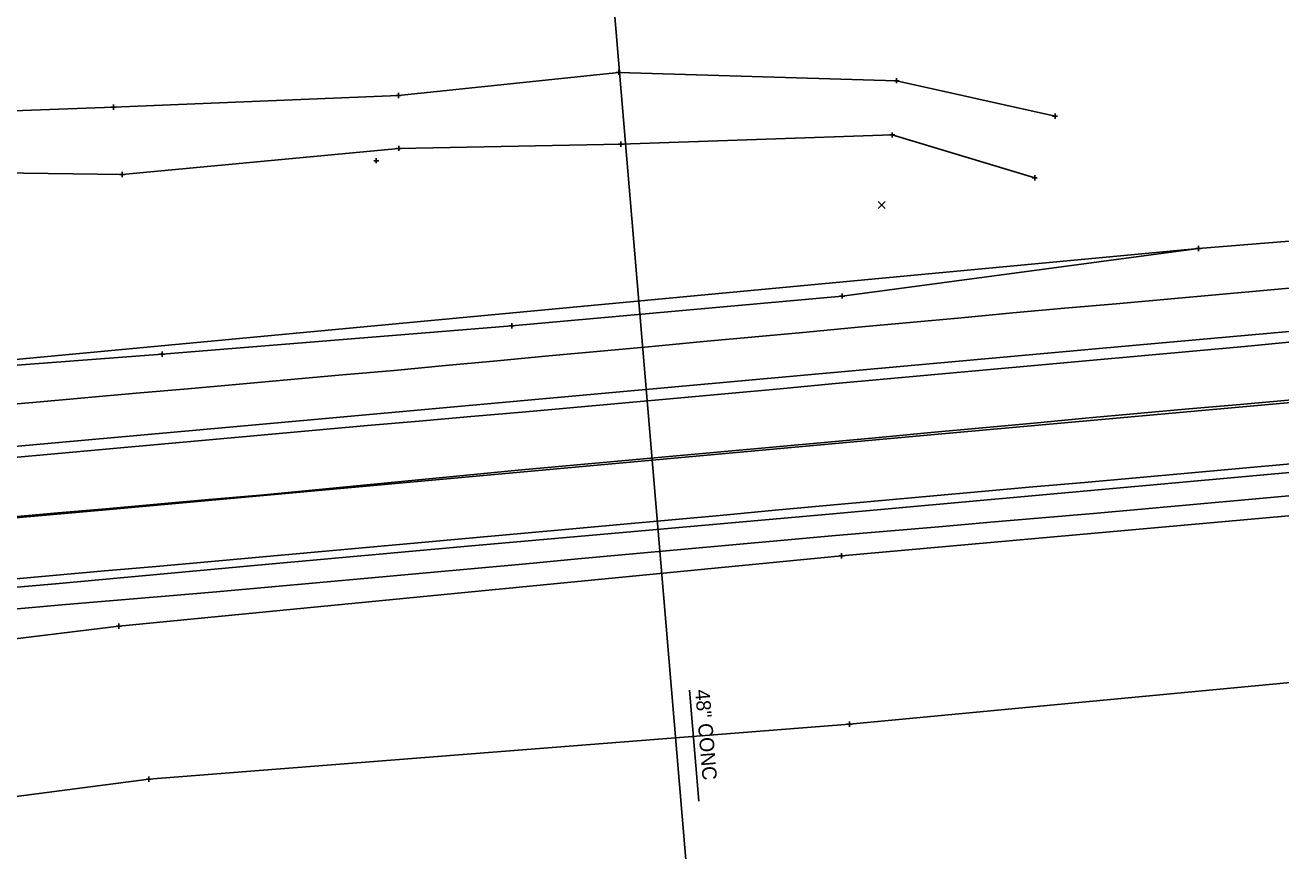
# Model space of a CAD drawing. Extents: x 207090 to 277928, y 600777 to 621109.
# Drawn here: x 261434.3 to 261676.8, y 612208.4 to 612367.8 of the extents above; entities that cross this region are included whole.
import ezdxf

# ---------------------------------------------------------------- set-up
doc = ezdxf.new("R2010")
doc.units = 0
for name, color, linetype in [('DR_X_Ditch', 7, 'Continuous'), ('DR_X_Storm_Sewer', 7, 'Continuous'), ('DR_X_Text', 7, 'Continuous'), ('PM_P_Edge_Line', 7, 'Continuous'), ('PM_P_Stop_Line', 7, 'Continuous'), ('PM_X_Edge_Line', 7, 'Continuous'), ('PM_X_Lane_Line', 7, 'Continuous'), ('PV_X_COP', 7, 'Continuous'), ('PV_X_EOP', 7, 'Continuous'), ('PV_X_Shoulder_Rumble_Strip', 7, 'Continuous'), ('SC_ProfileRun2', 7, 'Continuous'), ('SV_X_Toe_of_Slope', 7, 'Continuous')]:
    doc.layers.add(name, color=color, linetype=linetype)

msp = doc.modelspace()

# ---------------------------------------------------------------- linework, layer by layer
at = {"layer": 'DR_X_Ditch'}
msp.add_lwpolyline([(261203.79, 612197.21), (261326.07, 612205.04), (261458.14, 612222.26), (261593.47, 612232.9), (261720.84, 612244.93), (261848.4, 612257.12), (261858.55, 612256.91)], dxfattribs=at)
at = {"layer": 'DR_X_Storm_Sewer'}
msp.add_line((261547.33, 612379.42), (261572.44, 612081.43), dxfattribs=at)
at = {"layer": 'DR_X_Text'}
msp.add_line((261564.35, 612218), (261562.54, 612239.45), dxfattribs=at)
at = {"layer": 'PM_P_Edge_Line'}
for points in [[(261194.23, 612211.46), (261326.93, 612217.65), (261370.14, 612241.77), (261452.37, 612251.81), (261591.95, 612265.36), (261714.92, 612276.39), (261857.94, 612285.81), (262004.26, 612302.21), (262139.05, 612311.28), (262277.89, 612327.47), (262423.18, 612340.98), (262554.31, 612350.26), (262686.32, 612362.25)], [(261633.15, 612350.23), (261602.56, 612357.06), (261548.9, 612358.68), (261506.35, 612354.2), (261451.33, 612351.96), (261395.04, 612349.88), (261337.88, 612345.88), (261278.55, 612340.15), (261221.93, 612336.04)], [(262058.53, 612356.83), (261940.84, 612349.68), (261860.82, 612342.07), (261794.21, 612335.5), (261726.89, 612330.02), (261660.87, 612324.68), (261592.06, 612315.51), (261528.23, 612309.75), (261460.75, 612304.3), (261395.26, 612299.36), (261330.21, 612293.39), (261264.57, 612287.95), (261201.55, 612284), (261173.78, 612279.04)], [(261660.87, 612324.68), (261173.78, 612279.04)]]:
    msp.add_lwpolyline(points, dxfattribs=at)
at = {"layer": 'PM_P_Stop_Line'}
for p, q in [((261548.4, 612358.68), (261549.4, 612358.68)), ((261548.9, 612359.18), (261548.9, 612358.18)), ((261548.9, 612358.68), (261548.9, 612358.68)), ((261602.06, 612357.06), (261603.06, 612357.06)), ((261602.56, 612357.56), (261602.56, 612356.56)), ((261602.56, 612357.06), (261602.56, 612357.06)), ((261505.85, 612354.2), (261506.85, 612354.2)), ((261506.35, 612354.7), (261506.35, 612353.7)), ((261506.35, 612354.2), (261506.35, 612354.2)), ((261450.83, 612351.96), (261451.83, 612351.96)), ((261451.33, 612352.46), (261451.33, 612351.46)), ((261451.33, 612351.96), (261451.33, 612351.96)), ((261632.65, 612350.23), (261633.65, 612350.23)), ((261633.15, 612350.73), (261633.15, 612349.73)), ((261633.15, 612350.23), (261633.15, 612350.23)), ((261601.21, 612346.6), (261602.21, 612346.6)), ((261601.71, 612347.1), (261601.71, 612346.1)), ((261601.71, 612346.6), (261601.71, 612346.6)), ((261505.91, 612344.01), (261506.91, 612344.01)), ((261506.41, 612344.51), (261506.41, 612343.51)), ((261506.41, 612344.01), (261506.41, 612344.01)), ((261548.82, 612344.81), (261549.82, 612344.81)), ((261549.32, 612345.31), (261549.32, 612344.31)), ((261549.32, 612344.81), (261549.32, 612344.81)), ((261452.52, 612338.97), (261453.52, 612338.97)), ((261453.02, 612339.47), (261453.02, 612338.47)), ((261453.02, 612338.97), (261453.02, 612338.97)), ((261629.22, 612338.81), (261629.22, 612337.81)), ((261628.72, 612338.31), (261629.72, 612338.31)), ((261629.22, 612338.31), (261629.22, 612338.31)), ((261660.37, 612324.68), (261661.37, 612324.68)), ((261660.87, 612325.18), (261660.87, 612324.18)), ((261660.87, 612324.68), (261660.87, 612324.68)), ((261591.56, 612315.51), (261592.56, 612315.51)), ((261592.06, 612316.01), (261592.06, 612315.01)), ((261592.06, 612315.51), (261592.06, 612315.51)), ((261527.73, 612309.75), (261528.73, 612309.75)), ((261528.23, 612310.25), (261528.23, 612309.25)), ((261528.23, 612309.75), (261528.23, 612309.75)), ((261460.25, 612304.3), (261461.25, 612304.3)), ((261460.75, 612304.8), (261460.75, 612303.8)), ((261460.75, 612304.3), (261460.75, 612304.3)), ((261591.45, 612265.36), (261592.45, 612265.36)), ((261591.95, 612265.86), (261591.95, 612264.86)), ((261591.95, 612265.36), (261591.95, 612265.36)), ((261451.87, 612251.81), (261452.87, 612251.81)), ((261452.37, 612252.31), (261452.37, 612251.31)), ((261452.37, 612251.81), (261452.37, 612251.81)), ((261592.97, 612232.9), (261593.97, 612232.9)), ((261593.47, 612233.4), (261593.47, 612232.4)), ((261593.47, 612232.9), (261593.47, 612232.9)), ((261458.14, 612222.76), (261458.14, 612221.76)), ((261457.64, 612222.26), (261458.64, 612222.26)), ((261458.14, 612222.26), (261458.14, 612222.26))]:
    msp.add_line(p, q, dxfattribs=at)
at = {"layer": 'PM_X_Edge_Line'}
for p, q in [((261599.02, 612332.41), (261600.35, 612333.75)), ((261599.02, 612333.75), (261600.35, 612332.41))]:
    msp.add_line(p, q, dxfattribs=at)
for points in [[(261430.67, 612284.21), (261440.63, 612285.12), (261450.59, 612286.03), (261460.55, 612286.94), (261470.51, 612287.84), (261480.47, 612288.74), (261490.43, 612289.64), (261500.39, 612290.53), (261510.35, 612291.38), (261520.32, 612292.23), (261530.28, 612293.08), (261540.24, 612293.97), (261550.2, 612294.89), (261560.16, 612295.8), (261570.12, 612296.72), (261580.08, 612297.63), (261590.04, 612298.54), (261600, 612299.44), (261609.95, 612300.35), (261619.91, 612301.26), (261629.87, 612302.16), (261639.83, 612303.06), (261649.79, 612303.97), (261659.75, 612304.88), (261669.71, 612305.8), (261679.67, 612306.73)], [(261429.69, 612260.67), (261439.65, 612261.56), (261449.61, 612262.45), (261459.57, 612263.33), (261469.54, 612264.22), (261479.5, 612265.11), (261489.46, 612266.01), (261499.42, 612266.92), (261509.38, 612267.82), (261519.34, 612268.72), (261529.29, 612269.62), (261539.25, 612270.53), (261549.21, 612271.44), (261559.17, 612272.34), (261569.13, 612273.25), (261579.09, 612274.16), (261589.05, 612275.07), (261599.01, 612275.98), (261608.97, 612276.87), (261618.93, 612277.76), (261628.89, 612278.66), (261638.85, 612279.55), (261648.81, 612280.44), (261658.77, 612281.33), (261668.73, 612282.23), (261678.69, 612283.12)]]:
    msp.add_lwpolyline(points, dxfattribs=at)
at = {"layer": 'PM_X_Lane_Line'}
msp.add_lwpolyline([(262874.12, 612402.78), (262754.57, 612391.84), (262595.21, 612377.42), (262445.84, 612363.94), (262246.63, 612346.14), (262127.1, 612335.37), (261927.91, 612317.26), (261768.53, 612303.01), (261609.16, 612288.74), (261449.84, 612274.25), (261250.6, 612256.59), (261180.85, 612250.46), (260934.32, 612228.3), (260765.03, 612212.96), (260605.67, 612198.62), (260486.15, 612187.89), (260286.93, 612170.16), (260167.4, 612159.49), (260047.88, 612148.75), (259848.7, 612130.53), (259739.14, 612120.72), (259619.6, 612110.18), (259500.08, 612099.36), (259440.06, 612094.01)], dxfattribs=at)
at = {"layer": 'PV_X_COP'}
msp.add_lwpolyline([(261678.89, 612295.48), (261668.93, 612294.6), (261658.97, 612293.71), (261649, 612292.83), (261639.05, 612291.92), (261629.09, 612291), (261619.13, 612290.08), (261609.17, 612289.16), (261599.21, 612288.24), (261589.25, 612287.33), (261579.29, 612286.43), (261569.33, 612285.53), (261559.37, 612284.63), (261549.42, 612283.72), (261539.46, 612282.82), (261529.5, 612281.89), (261519.54, 612280.93), (261509.59, 612279.97), (261499.64, 612279.01), (261489.68, 612278.05), (261479.73, 612277.09), (261469.77, 612276.22), (261459.8, 612275.34), (261449.84, 612274.46), (261439.88, 612273.58), (261429.92, 612272.71)], dxfattribs=at)
at = {"layer": 'PV_X_EOP'}
for points in [[(261684.78, 612317.58), (261674.82, 612316.69), (261664.86, 612315.81), (261654.9, 612314.92), (261644.93, 612314.03), (261634.97, 612313.14), (261625.01, 612312.26), (261615.06, 612311.33), (261605.1, 612310.41), (261595.14, 612309.48), (261585.18, 612308.56), (261575.22, 612307.63), (261565.27, 612306.71), (261555.31, 612305.79), (261545.35, 612304.86), (261535.39, 612303.94), (261525.44, 612303.02), (261515.48, 612302.09), (261505.52, 612301.17), (261495.56, 612300.28), (261485.6, 612299.4), (261475.64, 612298.51), (261465.68, 612297.62), (261455.72, 612296.74), (261445.76, 612295.85), (261435.79, 612294.99), (261425.83, 612294.13)], [(261680.44, 612277.17), (261670.48, 612276.25), (261660.52, 612275.33), (261650.56, 612274.43), (261640.6, 612273.57), (261630.63, 612272.72), (261620.67, 612271.86), (261610.71, 612271), (261600.74, 612270.15), (261590.78, 612269.27), (261580.82, 612268.37), (261570.86, 612267.47), (261560.9, 612266.57), (261550.94, 612265.67), (261540.98, 612264.77), (261531.02, 612263.86), (261521.06, 612262.96), (261511.1, 612262.05), (261501.14, 612261.15), (261491.18, 612260.24), (261481.22, 612259.34), (261471.26, 612258.44), (261461.3, 612257.59), (261451.34, 612256.74), (261441.37, 612255.89), (261431.41, 612255.03)]]:
    msp.add_lwpolyline(points, dxfattribs=at)
at = {"layer": 'PV_X_Shoulder_Rumble_Strip'}
for points in [[(261171.77, 612263.54), (261191.64, 612265.01), (261242.4, 612269.66), (261300.22, 612274.78), (261389.86, 612282.66), (261479.48, 612290.75), (261561.24, 612298.1), (261648.8, 612306.02), (261758.4, 612315.82), (261840.04, 612323.18), (261929.7, 612331.26), (262039.34, 612341.21), (262119.09, 612348.61), (262217.41, 612357.48), (262227.03, 612358.33)], [(261709.04, 612284.22), (261669.2, 612280.62), (261629.37, 612277.01), (261589.54, 612273.42), (261549.68, 612269.86), (261519.77, 612267.26), (261479.94, 612263.63), (261440.14, 612259.95), (261410.24, 612257.38), (261370.44, 612253.73), (261340.55, 612251.09), (261310.62, 612248.57), (261270.78, 612244.98), (261230.94, 612241.4), (261191.1, 612237.84), (261170.6, 612235.95)]]:
    msp.add_lwpolyline(points, dxfattribs=at)
at = {"layer": 'SC_ProfileRun2'}
for p, q in [((261501.59, 612341.63), (261502.59, 612341.63)), ((261502.09, 612342.13), (261502.09, 612341.13)), ((261502.09, 612341.63), (261502.09, 612341.63))]:
    msp.add_line(p, q, dxfattribs=at)
at = {"layer": 'SV_X_Toe_of_Slope'}
for points in [[(261629.22, 612338.31), (261601.71, 612346.6), (261549.32, 612344.81), (261506.41, 612344.01), (261453.02, 612338.97), (261395.83, 612339.74), (261338.74, 612337.56), (261280.63, 612330.56), (261223.71, 612329)], [(261660.87, 612324.68), (261173.78, 612279.04)]]:
    msp.add_lwpolyline(points, dxfattribs=at)

# ---------------------------------------------------------------- texts
at = {"layer": 'DR_X_Text'}
msp.add_text('48" CONC', height=2.8, rotation=274.8155, dxfattribs=at).set_placement((261563.64, 612239.47))

doc.saveas('drawing.dxf')
